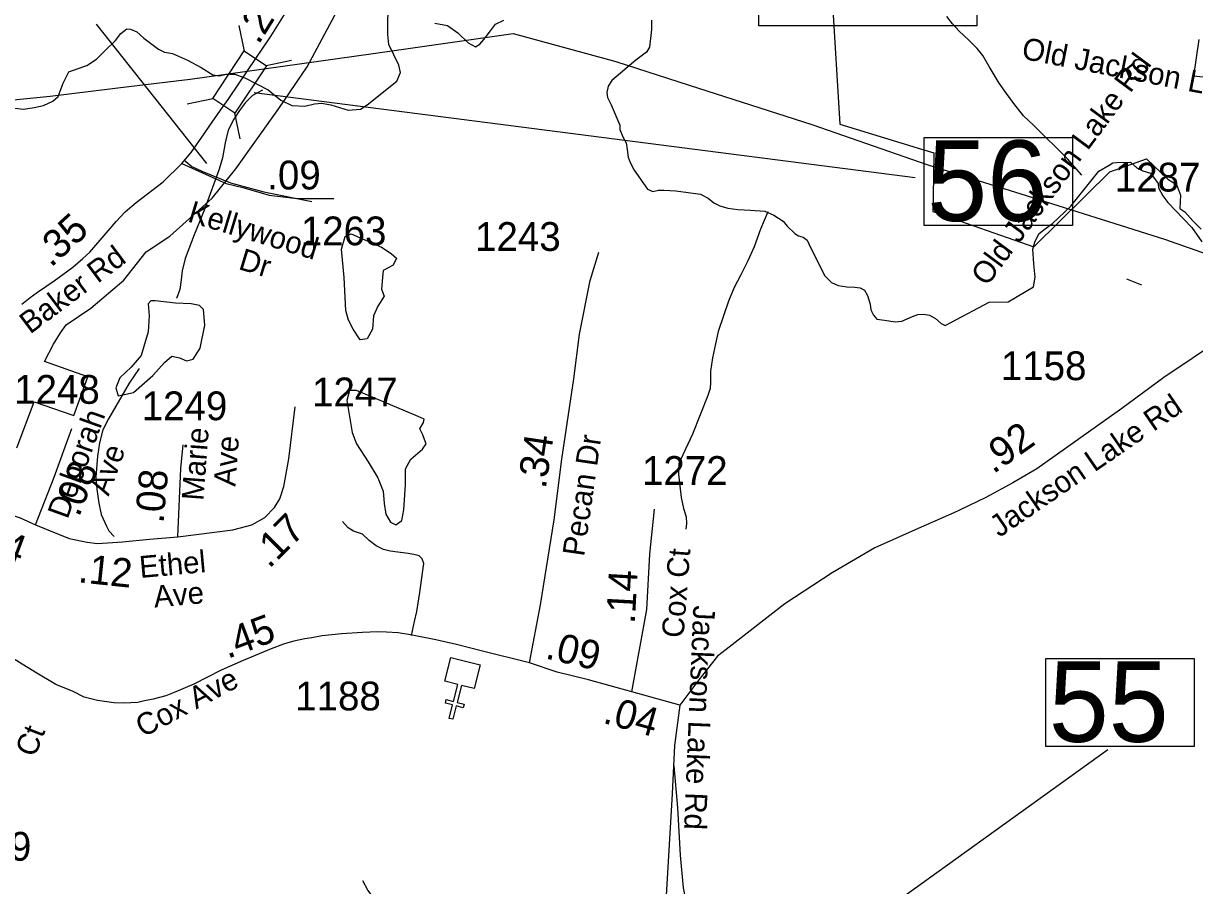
# Model space of a CAD drawing. Extents: x 1662474 to 1856135, y 779280 to 917889.
# Drawn here: x 1716644 to 1721731, y 797613 to 801357 of the extents above; entities that cross this region are included whole.
import ezdxf

# ---------------------------------------------------------------- set-up
doc = ezdxf.new("R2010")
doc.units = 0
for name, color, linetype in [('Exist Boundary Political City Limit New', 7, 'Continuous'), ('Exist Cultural Church CELL', 7, 'Continuous'), ('Exist Hydrographic Creek Single Shore', 7, 'Continuous'), ('Exist Hydrographic Misc Water Feature', 7, 'Continuous'), ('Exist Hydrographic Pond Under 1500 Sq Ft', 7, 'Continuous'), ('Exist Road Non-System Type 51', 7, 'Continuous'), ('Exist Road Non-System Type 51 Label', 7, 'Continuous'), ('Exist Road Secondary Mileage Hundredths English Label', 7, 'Continuous'), ('Exist Road Secondary Mileage Tenths English Label', 7, 'Continuous'), ('Exist Road Secondary Structure Private Number Label', 7, 'Continuous'), ('Exist Road Secondary Structure Standard Bridge CELL', 7, 'Continuous'), ('Exist Road Secondary Structure Standard Bridge Number Label', 7, 'Continuous'), ('Exist Road Secondary Type 51 Attributed', 7, 'Continuous'), ('Exist Road Secondary Type 51 Label', 7, 'Continuous'), ('Exist Road Secondary Type 51 Number Label', 7, 'Continuous'), ('Exist Utilities Electrical Transmission Line', 7, 'Continuous'), ('Map Preparation Boundary City Limit Buffer Line', 7, 'Continuous'), ('Prop Road Secondary Projected', 7, 'Continuous')]:
    doc.layers.add(name, color=color, linetype=linetype)

msp = doc.modelspace()

# ---------------------------------------------------------------- linework, layer by layer
at = {"layer": 'Exist Boundary Political City Limit New'}
for points in [[(1720123.8, 802010.3), (1720189.6, 800919.6), (1720525.5, 800817.1), (1720598.5, 800794.8), (1720596.6, 800688.9), (1720593.9, 800541.1), (1721033, 800386.5), (1721258.5, 800609.3), (1721362.6, 800712.1), (1721522.4, 800769), (1721614.4, 800681.3), (1721652.9, 800657.1), (1721669.2, 800611.6), (1721667.1, 800553.3), (1721688.6, 800539.3), (1721723.5, 800499.2), (1721759.8, 800463.9)], [(1716615.4, 799514.4), (1716691.5, 799713.8), (1716862.9, 799654.5), (1716924.2, 799822.6), (1716736.2, 799889.3), (1716774.8, 799963.9), (1716805.4, 800013.4), (1716830.4, 800048.3), (1716937.6, 800121.1), (1717080, 800242.2), (1717177.5, 800365.6), (1717280.5, 800433.2), (1717463.6, 800598), (1717567.4, 800726.4), (1717752.9, 800987.8), (1717877, 801169.2), (1718082.9, 801556.6)], [(1721873.4, 801112.2), (1721728.1, 801128.8), (1721751.2, 801287)]]:
    msp.add_lwpolyline(points, dxfattribs=at)
at = {"layer": 'Exist Cultural Church CELL'}
msp.add_lwpolyline([(1718601.4, 798468.3), (1718546.2, 798482.2), (1718527.5, 798408.4), (1718558.5, 798400.6), (1718554.5, 798385.1), (1718523.5, 798393), (1718508.7, 798334.7), (1718493.2, 798338.6), (1718508, 798396.9), (1718477, 798404.8), (1718480.9, 798420.3), (1718511.9, 798412.4), (1718530.7, 798486.2), (1718474.8, 798500.5), (1718501.1, 798603.7), (1718627.7, 798571.5)], close=True, dxfattribs=at)
at = {"layer": 'Exist Hydrographic Creek Single Shore'}
for points in [[(1717866, 800998.1), (1717908.9, 801007.6), (1717939.5, 801010.4), (1717978.9, 801003.1), (1718054.5, 800980.5), (1718108, 800985.5), (1718136.9, 801003.1), (1718266, 801106.8), (1718282.6, 801143.8), (1718274.1, 801175.8), (1718230.9, 801265.8), (1718226.6, 801309.1), (1718227.8, 801465.1)], [(1718430.4, 801357.7), (1718486.2, 801348.2), (1718530.6, 801316.5), (1718576, 801273.2), (1718607, 801255.3), (1718625.9, 801266.9), (1718643.2, 801287.4), (1718668.1, 801319.4), (1718693.9, 801354.6), (1718730.1, 801372.1)], [(1719371.8, 801371.1), (1719371.8, 801330.6), (1719363.6, 801253.5), (1719351, 801232.5), (1719303.5, 801197.3), (1719199.9, 801109.9), (1719183.4, 801084.8), (1719177.6, 801056.9), (1719180.8, 801036.2), (1719196.2, 801004.4), (1719235, 800915.4), (1719235.2, 800896.8), (1719247.9, 800864.8), (1719262.4, 800838), (1719266, 800809.9), (1719270.5, 800776.1), (1719279.6, 800753), (1719296.2, 800720.2), (1719355.2, 800637.2), (1719378.1, 800627.2), (1719402.8, 800632.5), (1719425.4, 800633.3), (1719477.2, 800630.4), (1719584.6, 800615.7), (1719618.8, 800598.4), (1719642.4, 800578.4), (1719669.1, 800565.1), (1719703.5, 800554.6), (1719746.6, 800548.8), (1719802.5, 800545.6), (1719864.8, 800541.4), (1719903, 800524.6), (1719944.2, 800498.1), (1719961.8, 800477.1), (1719993.9, 800444.1), (1720010.4, 800434.9), (1720030.9, 800428.8), (1720047.6, 800416.2), (1720056, 800399.7), (1720123.2, 800262.2), (1720153.1, 800232.5), (1720182.8, 800219.1), (1720220.4, 800213.6), (1720255.2, 800211.5), (1720278.1, 800208.4), (1720296.8, 800198.4), (1720310.1, 800175.3), (1720321.4, 800138.6), (1720324.5, 800113.4), (1720335.9, 800090), (1720350.5, 800073.4), (1720383.6, 800067.9), (1720430.9, 800060.6)], [(1716607.2, 800988.7), (1716644.5, 800984.8), (1716690.2, 800991.8), (1716731.4, 801001), (1716771.6, 801018.9), (1716795.5, 801040.4), (1716816.5, 801097.3), (1716842.1, 801146.9), (1716882.4, 801161.6), (1716919.6, 801175), (1716961.1, 801201.5), (1716999.1, 801239.1), (1717043.5, 801283.4), (1717067.1, 801314.1), (1717093.1, 801333.8), (1717108.9, 801333), (1717136.4, 801321.4), (1717167.6, 801293.9), (1717230.9, 801245.1), (1717257.6, 801232.5), (1717291.5, 801226.4), (1717356.6, 801197.3), (1717415.6, 801165.6), (1717466.4, 801133.3), (1717495.1, 801129.4), (1717525.1, 801136.4), (1717562.4, 801137.5), (1717605.6, 801121.2)], [(1717605.6, 801121.2), (1717707.2, 801068.4), (1717762.6, 801023.8), (1717810.4, 801001.2), (1717866, 800998.1)], [(1720430.9, 800060.6), (1720458.6, 800064), (1720506.1, 800084.8), (1720529.2, 800092.9), (1720553.9, 800094.8), (1720579.6, 800089.8), (1720604.9, 800076.1), (1720629.5, 800053.5), (1720647.1, 800045.1), (1720674.6, 800059.8), (1720838.1, 800146.7), (1720921.6, 800147.8), (1721031.4, 800212.6), (1721038.8, 800255.1), (1721032.4, 800313.1), (1721028.2, 800376.1), (1721036.6, 800406.8), (1721055, 800443), (1721076.8, 800462.9), (1721113, 800488.4), (1721193.8, 800562.9), (1721315.6, 800716.2), (1721359.1, 800741.7), (1721375.4, 800751.4), (1721392, 800753), (1721451.8, 800754.3), (1721480.1, 800729.6), (1721506.6, 800717.2), (1721538.6, 800706.8), (1721573, 800662.4), (1721573.9, 800642.8), (1721592.5, 800608.4), (1721614, 800579.8), (1721682.2, 800508.1), (1721718.5, 800470.3), (1721762, 800409.1)]]:
    msp.add_lwpolyline(points, dxfattribs=at)
at = {"layer": 'Exist Hydrographic Misc Water Feature'}
msp.add_line((1721434.4, 800248.1), (1721500.4, 800221.4), dxfattribs=at)
for points in [[(1721240.6, 800698), (1721179.3, 800768.7), (1721032.7, 800914.1), (1720987.2, 800956.6), (1720945.5, 801008.9), (1720914, 801053.2), (1720882.4, 801097.5), (1720839.1, 801170), (1720811.6, 801218.3), (1720785.8, 801248.6), (1720750.1, 801284.8), (1720708.5, 801323.3), (1720678.8, 801355.5), (1720655, 801387.8)], [(1717683.2, 801067.8), (1717638.9, 801044.2), (1717608.6, 801014.5), (1717582.3, 800978.8), (1717557.9, 800941), (1717533.5, 800893.2), (1717520.9, 800839.3), (1717508.3, 800773.3), (1717493.9, 800723.6), (1717432.3, 800554), (1717409.6, 800496.2), (1717385.1, 800438.5), (1717346.2, 800336.8), (1717333.7, 800282.9), (1717329.2, 800242.9), (1717322.9, 800201), (1717314.6, 800179.1), (1717308.5, 800163.1)], [(1719876.8, 800538.9), (1719846.1, 800463.2), (1719817.3, 800387.4), (1719790.8, 800325.7), (1719760.1, 800265.9), (1719731.6, 800210.2), (1719707, 800150.4), (1719661.8, 800018.8), (1719649.3, 799964.9), (1719636.8, 799904.9), (1719628.2, 799847.1), (1719627.7, 799799.1), (1719627.5, 799771), (1719617.2, 799741.2), (1719549.5, 799573.7), (1719498.5, 799462.1), (1719490.3, 799444.2), (1719489.9, 799400.2), (1719500.9, 799298), (1719510.6, 799250), (1719522.2, 799213.9), (1719523.9, 799185.9), (1719521.7, 799159.9)], [(1717147.5, 799858.5), (1717102.9, 799794.9), (1717013.5, 799639.7), (1716989, 799591.9), (1716974.5, 799536.1), (1716965.9, 799478.1), (1716959, 799386.1), (1716962.5, 799334.1), (1716971.9, 799274), (1716981.5, 799223.9), (1717005, 799173.6), (1717014.9, 799153.6), (1717038.6, 799129.3)], [(1718738.9, 796562.4), (1718705.3, 796622.8), (1718693.9, 796672.9), (1718652.8, 796773.3), (1718552.9, 797002.4), (1718537.3, 797034.5), (1718519.5, 797064.7), (1718440.5, 797169.5), (1718367.4, 797264.2), (1718320.1, 797332.6), (1718280.6, 797399.1), (1718209.6, 797513.8), (1718164.1, 797560.2), (1718140.4, 797592.5), (1718118.8, 797632.7)]]:
    msp.add_lwpolyline(points, dxfattribs=at)
at = {"layer": 'Exist Hydrographic Pond Under 1500 Sq Ft'}
for points in [[(1718044.9, 800110.4), (1718037.1, 800253.4), (1718025.5, 800377.1), (1718041, 800431.2), (1718068.1, 800442.8), (1718199.5, 800384.8), (1718242, 800357.7), (1718265.2, 800338.4), (1718249.8, 800307.5), (1718207.2, 800284.3), (1718203.4, 800253.4), (1718199.5, 800203.2), (1718211.1, 800172.3), (1718184, 800129.7), (1718164.7, 800087.2), (1718160.8, 800029.3), (1718137.6, 799986.8), (1718106.7, 799982.9), (1718075.8, 800029.3), (1718056.5, 800067.9), (1718044.9, 800110.4)], [(1717304.6, 800142.4), (1717215.8, 800152.6), (1717198.1, 800152.6), (1717185.4, 800139.9), (1717190.4, 800086.7), (1717185.4, 800018.2), (1717154.9, 799914.3), (1717111.8, 799863.6), (1717063.6, 799817.9), (1717045.9, 799774.8), (1717056, 799739.3), (1717122, 799754.5), (1717205.7, 799828.1), (1717256.4, 799883.8), (1717289.4, 799911.7), (1717322.3, 799904.1), (1717352.8, 799891.4), (1717380.7, 799899.1), (1717411.1, 799947.2), (1717431.4, 800046.1), (1717426.3, 800114.6), (1717408.6, 800132.3), (1717373.1, 800139.9), (1717304.6, 800142.4)], [(1718358, 799650.5), (1718091.3, 799762.6), (1718060.3, 799762.6), (1718048.7, 799720.1), (1718071.9, 799581), (1718091.3, 799530.8), (1718141.5, 799453.5), (1718184, 799383.9), (1718207.2, 799325.9), (1718211.1, 799271.8), (1718218.8, 799225.5), (1718238.2, 799190.7), (1718261.4, 799179.1), (1718288.4, 799198.4), (1718296.2, 799244.8), (1718303.9, 799353), (1718303.9, 799422.5), (1718327.1, 799465.1), (1718377.4, 799507.6), (1718392.8, 799530.8), (1718377.4, 799573.3), (1718365.8, 799596.4), (1718381.2, 799623.5), (1718385.1, 799639), (1718358, 799650.5)]]:
    msp.add_lwpolyline(points, dxfattribs=at)
at = {"layer": 'Exist Road Non-System Type 51'}
for points in [[(1717340.6, 800764.2), (1717375.8, 800736.4), (1717419.1, 800715.2), (1717543.8, 800664.5), (1717687.6, 800625.7), (1717896.5, 800584.2)], [(1718329.9, 798698.2), (1718343.1, 798760.1), (1718352.9, 798802.4), (1718365.5, 798884.8), (1718378.1, 798970.4), (1718383.4, 799011.2), (1718376, 799031.5), (1718363.4, 799045.1), (1718340, 799050.4), (1718314.9, 799055.6), (1718237.6, 799065.1), (1718208, 799072.7), (1718176.5, 799088.4), (1718145.6, 799111.8), (1718116.4, 799139.1), (1718078.4, 799152.4), (1718055, 799166.7), (1718029.9, 799193.9)]]:
    msp.add_lwpolyline(points, dxfattribs=at)
at = {"layer": 'Exist Road Secondary Mileage Hundredths English Label'}
msp.add_line((1717441.1, 800748.2), (1716961.9, 801353.6), dxfattribs=at)
at = {"layer": 'Exist Road Secondary Structure Private Number Label'}
msp.add_lwpolyline([(1719837.9, 801732.7), (1720784.3, 801732.7), (1720784.3, 801346.2), (1719837.9, 801346.2)], close=True, dxfattribs=at)
at = {"layer": 'Exist Road Secondary Structure Standard Bridge CELL'}
for p, q in [((1717603.7, 801237.4), (1717581.2, 801348.3)), ((1717698, 801174.8), (1717808.9, 801197.2)), ((1717355.2, 801008.7), (1717466.1, 801031.1)), ((1717585, 800856.2), (1717562.6, 800967.1))]:
    msp.add_line(p, q, dxfattribs=at)
msp.add_lwpolyline([(1717466.1, 801031.1), (1717603.2, 801237.7), (1717699.7, 801173.6), (1717562.6, 800967.1)], close=True, dxfattribs=at)
at = {"layer": 'Exist Road Secondary Structure Standard Bridge Number Label'}
for p, q in [((1717646.6, 801057.9), (1720516.6, 800687.5)), ((1719624.9, 796960.8), (1721353.5, 798204.2))]:
    msp.add_line(p, q, dxfattribs=at)
for points in [[(1720557, 800861.8), (1721201.1, 800861.8), (1721201.1, 800479.5), (1720557, 800479.5)], [(1721085, 798599.3), (1721729.1, 798599.3), (1721729.1, 798217), (1721085, 798217)]]:
    msp.add_lwpolyline(points, close=True, dxfattribs=at)
at = {"layer": 'Exist Road Secondary Type 51 Attributed'}
msp.add_line((1719495, 798396.1), (1719287, 798454.6), dxfattribs=at)
for points in [[(1717584.8, 801102.8), (1717720.8, 801304.1), (1717800.5, 801431.3), (1717851.4, 801511.1), (1717872.7, 801552.3), (1717887.8, 801591.1), (1717898.1, 801656.2), (1717900.5, 801707), (1717907.3, 801750.1), (1717900.4, 801798.7), (1717881.2, 801852.2), (1717867.4, 801882.2), (1717859, 801897.4), (1717845.5, 801915.3), (1717813.6, 801963.3), (1717772, 802033.7)], [(1717332.3, 800748.6), (1717373.3, 800797.1), (1717429.4, 800877.2), (1717450.9, 800909.6), (1717499.4, 800980.9), (1717533, 801026.6), (1717584.8, 801102.8)], [(1716637.8, 800137.4), (1716673.6, 800166.5), (1716705.1, 800189.8), (1716778.2, 800239.7), (1716858.8, 800298.2), (1716902.5, 800336.6), (1716932, 800363.5), (1717003.5, 800445.8), (1717046.3, 800496.9), (1717085.9, 800539.6), (1717133.4, 800579.9), (1717251.3, 800669.5), (1717332.3, 800748.6)], [(1717332.3, 800748.6), (1717450.6, 800694.9), (1717525.3, 800662), (1717597.1, 800644.1), (1717712.2, 800610.9), (1717833.7, 800596.9), (1717992.6, 800596.9)], [(1718841.8, 798579.5), (1718890.5, 798831.3), (1718949, 799201.5), (1718982, 799464.7), (1719034.4, 799813.8), (1719059.5, 800007), (1719105, 800240.8), (1719144, 800364.2)], [(1721847.2, 799986.7), (1721597.6, 799819.7), (1721415.3, 799684.3), (1721260.1, 799574.5), (1721046.3, 799423.3), (1720941.6, 799362), (1720824.5, 799298.1), (1720709.8, 799243.7), (1720685.6, 799232), (1720543.5, 799168.6), (1720341.6, 799079.6), (1720157.4, 798971.3), (1719951.6, 798836), (1719696.8, 798637.6), (1719659, 798608.6), (1719577.7, 798505.8), (1719495, 798396.1)], [(1717314.2, 799127), (1717553.5, 799157.6), (1717636, 799178.8), (1717692.5, 799211.8), (1717734.9, 799254.1), (1717758.5, 799291.8), (1717775, 799345.9), (1717796.2, 799466), (1717824.4, 799691.9)], [(1716696.7, 799179.6), (1716777.2, 799385.9), (1716854.9, 799597.8)], [(1717314.2, 799127), (1717328.4, 799423.6), (1717337.8, 799527.2)], [(1716241.6, 799300), (1716521.7, 799244.9), (1716630.5, 799210), (1716696.7, 799179.6)], [(1719287, 798454.6), (1719352, 798811.8), (1719365, 799052.1), (1719384.5, 799247)], [(1716696.7, 799179.6), (1716843.1, 799120), (1716920.9, 799103.5), (1716965.6, 799098.8), (1717074, 799105.8), (1717191.7, 799117.6), (1717314.2, 799127)], [(1718841.8, 798579.5), (1718632.4, 798632.1), (1718524.7, 798659.5), (1718435.2, 798680.4), (1718325.3, 798702), (1718271.3, 798710.6), (1718221.5, 798713.3), (1718184.1, 798714), (1718117.4, 798712.4), (1718025.4, 798705.8), (1717941.2, 798696.7), (1717897, 798689.3), (1717866.7, 798684.1), (1717818.9, 798674.2), (1717792.2, 798666.9), (1717773.4, 798661), (1717719.8, 798641.4), (1717598.6, 798590.4), (1717503.6, 798547.9), (1717384.6, 798488), (1717299.6, 798450.9), (1717262.5, 798436.2), (1717208.1, 798421.6), (1717170.3, 798415.4), (1717140.7, 798408), (1717110.3, 798406.1), (1717079.8, 798404.7), (1717037.1, 798406.1), (1716966.2, 798417.1), (1716908.6, 798431.5), (1716859.6, 798454.8), (1716784.5, 798485.5), (1716695.2, 798539.9), (1716559.3, 798622.9)], [(1719287, 798454.6), (1719098.5, 798506.5), (1718962, 798539), (1718841.8, 798579.5)], [(1719495, 798396.1), (1719472.4, 798221), (1719462, 798011.5), (1719422.6, 797348.8), (1719428.5, 797268.6), (1719435.4, 797221.5), (1719529.4, 796979.2), (1719563, 796913.3)]]:
    msp.add_lwpolyline(points, dxfattribs=at)
at = {"layer": 'Exist Utilities Electrical Transmission Line'}
msp.add_lwpolyline([(1716296.5, 800994.3), (1716760.9, 801042), (1717113.7, 801085), (1717368, 801115.3), (1718163.6, 801226.5), (1718770.7, 801313.9), (1719216.9, 801191.9), (1719535.5, 801089.6), (1720069, 800918.2), (1720572.2, 800743.5), (1720976.4, 800617.8), (1721599.6, 800419.7), (1721946, 800298.7)], dxfattribs=at)
at = {"layer": 'Map Preparation Boundary City Limit Buffer Line'}
for points in [[(1720123.8, 802010.3), (1720189.6, 800919.6), (1720525.5, 800817.1), (1720598.5, 800794.8), (1720596.6, 800688.9), (1720593.9, 800541.1), (1721033, 800386.5), (1721258.5, 800609.3), (1721362.6, 800712.1), (1721522.4, 800769), (1721614.4, 800681.3), (1721652.9, 800657.1), (1721669.2, 800611.6), (1721667.1, 800553.3), (1721688.6, 800539.3), (1721723.5, 800499.2), (1721759.8, 800463.9)], [(1716615.4, 799514.4), (1716691.5, 799713.8), (1716862.9, 799654.5), (1716924.2, 799822.6), (1716736.2, 799889.3), (1716774.8, 799963.9), (1716805.4, 800013.4), (1716830.4, 800048.3), (1716937.6, 800121.1), (1717080, 800242.2), (1717177.5, 800365.6), (1717280.5, 800433.2), (1717463.6, 800598), (1717567.4, 800726.4), (1717752.9, 800987.8), (1717877, 801169.2), (1718082.9, 801556.6)], [(1721873.4, 801112.2), (1721728.1, 801128.8), (1721751.2, 801287)]]:
    msp.add_lwpolyline(points, dxfattribs=at)
at = {"layer": 'Prop Road Secondary Projected'}
msp.add_lwpolyline([(1719590.7, 797187.8), (1719563, 797350.6), (1719533.4, 797493.1), (1719511.2, 797602.2), (1719498.2, 797744.7), (1719487.1, 797950.1), (1719470.5, 798133.2)], dxfattribs=at)

# ---------------------------------------------------------------- texts
at = {"layer": 'Exist Road Non-System Type 51 Label'}
for rotation, p in [(349.0131, (1720975.5, 801204.9)), (53.4678, (1720829, 800211.7))]:
    msp.add_text('Old Jackson Lake Rd', height=95, rotation=rotation, dxfattribs=at).set_placement(p)
at = {"layer": 'Exist Road Secondary Mileage Hundredths English Label'}
for s, rotation, p in [('.35', 42.3805, (1716763.3, 800294.2)), ('.08', 68.7096, (1716885.2, 799209.3)), ('.08', 84.8014, (1717252.4, 799183.7)), ('.17', 44.9778, (1717711.1, 798986.2)), ('.12', 353.9959, (1716878.7, 798930.3)), ('.09', 346.6176, (1718906.7, 798599.9)), ('.04', 344.3028, (1719156.3, 798320.2))]:
    msp.add_text(s, height=125, rotation=rotation, dxfattribs=at).set_placement(p)
at = {"layer": 'Exist Road Secondary Mileage Tenths English Label'}
for s, rotation, p in [('.28', 57.9606, (1717665.2, 801261.6)), ('.09', 359.976, (1717703.1, 800636.2)), ('.92', 35.2677, (1720856.5, 799398.2)), ('.34', 81.4638, (1718912.5, 799333)), ('.04 ', 339.316, (1716408.4, 799087.3)), ('.14', 86.9036, (1719299.3, 798747.9)), ('.45', 20.6075, (1717530.7, 798596.6))]:
    msp.add_text(s, height=125, rotation=rotation, dxfattribs=at).set_placement(p)
at = {"layer": 'Exist Road Secondary Structure Standard Bridge Number Label'}
for s, p in [('56', (1720569.5, 800499.3)), ('55', (1721097.6, 798236.8))]:
    msp.add_text(s, height=350, dxfattribs=at).set_placement(p)
at = {"layer": 'Exist Road Secondary Type 51 Label'}
for s, rotation, p in [('Kellywood', 343.1154, (1717353.3, 800497.8)), ('Baker Rd', 36.8772, (1716673.2, 800005.5)), (' Dr', 343.1154, (1717540.1, 800301.4)), ('Jackson Lake Rd', 34.5161, (1720882.6, 799122.3)), ('Deborah', 70.1253, (1716835.7, 799200.8)), ('Marie', 85.7345, (1717426, 799282.3)), (' Ave', 85.7345, (1717562.1, 799309)), ('Pecan Dr', 81.8092, (1719079.1, 799039.1)), (' Ave', 70.1253, (1717002.1, 799268)), ('Ethel', 5.1635, (1717151.7, 798948.4)), ('Cox Ct', 85.5133, (1719510.9, 798685.9)), (' Ave', 5.1635, (1717178.4, 798816.6)), ('Jackson Lake Rd', 267.6238, (1719553.9, 798830.2)), ('Cox Ave', 28.0332, (1717163.7, 798254.3)), (' Ct', 68.7471, (1716681.3, 798132.9))]:
    msp.add_text(s, height=95, rotation=rotation, dxfattribs=at).set_placement(p)
at = {"layer": 'Exist Road Secondary Type 51 Number Label'}
for s, p in [('1287', (1721384.4, 800627.1)), ('1263', (1717848.9, 800393.6)), ('1243', (1718605.8, 800369.2)), ('1158', (1720889.3, 799807.8)), ('1248', (1716603.9, 799705.1)), ('1247', (1717898, 799694.1)), ('1249', (1717157.9, 799633.8)), ('1272', (1719330.8, 799352.8)), ('1188', (1717824.7, 798373.4)), ('1189', (1716306.8, 797720.6))]:
    msp.add_text(s, height=125, dxfattribs=at).set_placement(p)

doc.saveas('drawing.dxf')
